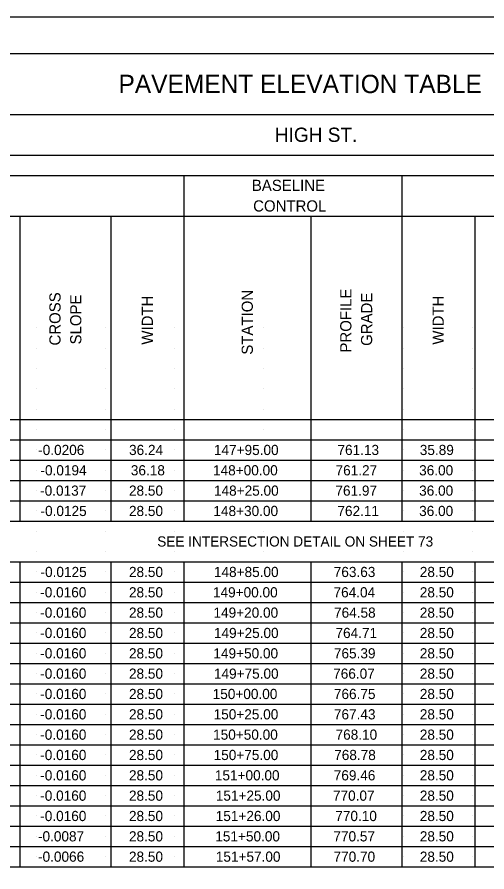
# Model space of a CAD drawing. Extents: x -15.4 to 18.6, y -12.6 to 9.4.
# Drawn here: x -2.5 to 3.96, y -2.38 to 9.39 of the extents above; entities that cross this region are included whole.
import ezdxf

# ---------------------------------------------------------------- set-up
doc = ezdxf.new("R2010")
doc.units = 0
for name, color, linetype in [('SH_Border', 7, 'Continuous'), ('SH_Cut_Line', 7, 'Continuous'), ('SH_Data', 7, 'Continuous'), ('SH_Text', 7, 'Continuous')]:
    doc.layers.add(name, color=color, linetype=linetype)

msp = doc.modelspace()

# ---------------------------------------------------------------- linework, layer by layer
at = {"layer": 'SH_Border'}
msp.add_lwpolyline([(-13.357, 8.888), (18.143, 8.888), (18.143, -12.112), (-13.357, -12.112)], close=True, dxfattribs=at)
at = {"layer": 'SH_Cut_Line'}
msp.add_lwpolyline([(-15.357, -12.612), (18.643, -12.612), (18.643, 9.388), (-15.357, 9.388)], close=True, dxfattribs=at)
at = {"layer": 'SH_Data'}
for p, q in [((-10.059, 8.888), (13.939, 8.888)), ((-8.906, 8.048), (12.061, 8.048)), ((-8.906, 7.488), (12.061, 7.488)), ((-10.059, 7.208), (13.939, 7.208)), ((-0.21, 7.208), (-0.21, 2.448)), ((2.788, 7.208), (2.788, 2.448)), ((-10.059, 6.648), (12.637, 6.648)), ((-2.466, 6.648), (-2.466, 2.448)), ((-1.214, 6.648), (-1.214, 2.448)), ((1.536, 6.648), (1.536, 2.448)), ((3.793, 6.648), (3.793, 2.448)), ((-2.232, 5.108), (-2.232, 5.108)), ((-1.282, 5.108), (-1.282, 5.108)), ((-0.332, 5.108), (-0.332, 5.108)), ((0.893, 5.108), (0.893, 5.108)), ((2.818, 5.108), (2.818, 5.108)), ((3.768, 5.108), (3.768, 5.108)), ((-2.232, 4.828), (-2.232, 4.828)), ((-1.282, 4.828), (-1.282, 4.828)), ((-0.332, 4.828), (-0.332, 4.828)), ((0.893, 4.828), (0.893, 4.828)), ((2.818, 4.828), (2.818, 4.828)), ((3.768, 4.828), (3.768, 4.828)), ((-2.232, 4.548), (-2.232, 4.548)), ((-1.282, 4.548), (-1.282, 4.548)), ((-0.332, 4.548), (-0.332, 4.548)), ((0.893, 4.548), (0.893, 4.548)), ((2.818, 4.548), (2.818, 4.548)), ((3.768, 4.548), (3.768, 4.548)), ((-2.232, 4.268), (-2.232, 4.268)), ((-1.282, 4.268), (-1.282, 4.268)), ((-0.332, 4.268), (-0.332, 4.268)), ((0.893, 4.268), (0.893, 4.268)), ((2.818, 4.268), (2.818, 4.268)), ((3.768, 4.268), (3.768, 4.268)), ((-2.232, 3.988), (-2.232, 3.988)), ((-1.282, 3.988), (-1.282, 3.988)), ((-0.332, 3.988), (-0.332, 3.988)), ((0.893, 3.988), (0.893, 3.988)), ((2.818, 3.988), (2.818, 3.988)), ((3.768, 3.988), (3.768, 3.988)), ((-10.059, 3.848), (13.939, 3.848)), ((-2.232, 3.708), (-2.232, 3.708)), ((-1.282, 3.708), (-1.282, 3.708)), ((-0.332, 3.708), (-0.332, 3.708)), ((0.893, 3.708), (0.893, 3.708)), ((2.818, 3.708), (2.818, 3.708)), ((3.768, 3.708), (3.768, 3.708)), ((-10.059, 3.568), (13.939, 3.568)), ((-2.232, 3.428), (-2.232, 3.428)), ((-1.282, 3.428), (-1.282, 3.428)), ((-0.332, 3.428), (-0.332, 3.428)), ((0.893, 3.428), (0.893, 3.428)), ((2.818, 3.428), (2.818, 3.428)), ((3.768, 3.428), (3.768, 3.428)), ((-10.059, 3.288), (13.939, 3.288)), ((-2.232, 3.148), (-2.232, 3.148)), ((-1.282, 3.148), (-1.282, 3.148)), ((-0.332, 3.148), (-0.332, 3.148)), ((0.893, 3.148), (0.893, 3.148)), ((2.818, 3.148), (2.818, 3.148)), ((3.768, 3.148), (3.768, 3.148)), ((-10.059, 3.008), (13.939, 3.008)), ((-2.232, 2.868), (-2.232, 2.868)), ((-1.282, 2.868), (-1.282, 2.868)), ((-0.332, 2.868), (-0.332, 2.868)), ((0.893, 2.868), (0.893, 2.868)), ((2.818, 2.868), (2.818, 2.868)), ((3.768, 2.868), (3.768, 2.868)), ((-10.059, 2.728), (13.939, 2.728)), ((-2.232, 2.588), (-2.232, 2.588)), ((-1.282, 2.588), (-1.282, 2.588)), ((-0.332, 2.588), (-0.332, 2.588)), ((0.893, 2.588), (0.893, 2.588)), ((2.818, 2.588), (2.818, 2.588)), ((3.768, 2.588), (3.768, 2.588)), ((-10.059, 2.448), (13.939, 2.448)), ((-2.232, 2.308), (-2.232, 2.308)), ((-1.282, 2.308), (-1.282, 2.308)), ((-0.332, 2.308), (-0.332, 2.308)), ((0.893, 2.308), (0.893, 2.308)), ((2.818, 2.308), (2.818, 2.308)), ((3.768, 2.308), (3.768, 2.308)), ((-2.232, 2.028), (-2.232, 2.028)), ((-1.282, 2.028), (-1.282, 2.028)), ((-0.332, 2.028), (-0.332, 2.028)), ((0.893, 2.028), (0.893, 2.028)), ((2.818, 2.028), (2.818, 2.028)), ((3.768, 2.028), (3.768, 2.028)), ((-10.059, 1.888), (13.939, 1.888)), ((-2.466, 1.888), (-2.466, -2.312)), ((-1.214, 1.888), (-1.214, -2.312)), ((-0.21, 1.888), (-0.21, -2.312)), ((1.536, 1.888), (1.536, -2.312)), ((2.788, 1.888), (2.788, -2.312)), ((3.793, 1.888), (3.793, -2.312)), ((-2.232, 1.748), (-2.232, 1.748)), ((-1.282, 1.748), (-1.282, 1.748)), ((-0.332, 1.748), (-0.332, 1.748)), ((0.893, 1.748), (0.893, 1.748)), ((2.818, 1.748), (2.818, 1.748)), ((3.768, 1.748), (3.768, 1.748)), ((-10.059, 1.608), (13.939, 1.608)), ((-2.232, 1.468), (-2.232, 1.468)), ((-1.282, 1.468), (-1.282, 1.468)), ((-0.332, 1.468), (-0.332, 1.468)), ((0.893, 1.468), (0.893, 1.468)), ((2.818, 1.468), (2.818, 1.468)), ((3.768, 1.468), (3.768, 1.468)), ((-10.059, 1.328), (13.939, 1.328)), ((-2.232, 1.188), (-2.232, 1.188)), ((-1.282, 1.188), (-1.282, 1.188)), ((-0.332, 1.188), (-0.332, 1.188)), ((0.893, 1.188), (0.893, 1.188)), ((2.818, 1.188), (2.818, 1.188)), ((3.768, 1.188), (3.768, 1.188)), ((-10.059, 1.048), (13.939, 1.048)), ((-2.232, 0.908), (-2.232, 0.908)), ((-1.282, 0.908), (-1.282, 0.908)), ((-0.332, 0.908), (-0.332, 0.908)), ((0.893, 0.908), (0.893, 0.908)), ((2.818, 0.908), (2.818, 0.908)), ((3.768, 0.908), (3.768, 0.908)), ((-10.059, 0.768), (13.939, 0.768)), ((-2.232, 0.628), (-2.232, 0.628)), ((-1.282, 0.628), (-1.282, 0.628)), ((-0.332, 0.628), (-0.332, 0.628)), ((0.893, 0.628), (0.893, 0.628)), ((2.818, 0.628), (2.818, 0.628)), ((3.768, 0.628), (3.768, 0.628)), ((-10.059, 0.488), (13.939, 0.488)), ((-2.232, 0.348), (-2.232, 0.348)), ((-1.282, 0.348), (-1.282, 0.348)), ((-0.332, 0.348), (-0.332, 0.348)), ((0.893, 0.348), (0.893, 0.348)), ((2.818, 0.348), (2.818, 0.348)), ((3.768, 0.348), (3.768, 0.348)), ((-10.059, 0.208), (13.939, 0.208)), ((-2.232, 0.068), (-2.232, 0.068)), ((-1.282, 0.068), (-1.282, 0.068)), ((-0.332, 0.068), (-0.332, 0.068)), ((0.893, 0.068), (0.893, 0.068)), ((2.818, 0.068), (2.818, 0.068)), ((3.768, 0.068), (3.768, 0.068)), ((-10.059, -0.072), (13.939, -0.072)), ((-2.232, -0.212), (-2.232, -0.212)), ((-1.282, -0.212), (-1.282, -0.212)), ((-0.332, -0.212), (-0.332, -0.212)), ((0.893, -0.212), (0.893, -0.212)), ((2.818, -0.212), (2.818, -0.212)), ((3.768, -0.212), (3.768, -0.212)), ((-10.059, -0.352), (13.939, -0.352)), ((-2.232, -0.492), (-2.232, -0.492)), ((-1.282, -0.492), (-1.282, -0.492)), ((-0.332, -0.492), (-0.332, -0.492)), ((0.893, -0.492), (0.893, -0.492)), ((2.818, -0.492), (2.818, -0.492)), ((3.768, -0.492), (3.768, -0.492)), ((-10.059, -0.632), (13.939, -0.632)), ((-2.232, -0.772), (-2.232, -0.772)), ((-1.282, -0.772), (-1.282, -0.772)), ((-0.332, -0.772), (-0.332, -0.772)), ((0.893, -0.772), (0.893, -0.772)), ((2.818, -0.772), (2.818, -0.772)), ((3.768, -0.772), (3.768, -0.772)), ((-10.059, -0.912), (13.939, -0.912)), ((-2.232, -1.052), (-2.232, -1.052)), ((-1.282, -1.052), (-1.282, -1.052)), ((-0.332, -1.052), (-0.332, -1.052)), ((0.893, -1.052), (0.893, -1.052)), ((2.818, -1.052), (2.818, -1.052)), ((3.768, -1.052), (3.768, -1.052)), ((-10.059, -1.192), (13.939, -1.192)), ((-2.232, -1.332), (-2.232, -1.332)), ((-1.282, -1.332), (-1.282, -1.332)), ((-0.332, -1.332), (-0.332, -1.332)), ((0.893, -1.332), (0.893, -1.332)), ((2.818, -1.332), (2.818, -1.332)), ((3.768, -1.332), (3.768, -1.332)), ((-10.059, -1.472), (13.939, -1.472)), ((-2.232, -1.612), (-2.232, -1.612)), ((-1.282, -1.612), (-1.282, -1.612)), ((-0.332, -1.612), (-0.332, -1.612)), ((0.893, -1.612), (0.893, -1.612)), ((2.818, -1.612), (2.818, -1.612)), ((3.768, -1.612), (3.768, -1.612)), ((-10.059, -1.752), (13.939, -1.752)), ((-2.232, -1.892), (-2.232, -1.892)), ((-1.282, -1.892), (-1.282, -1.892)), ((-0.332, -1.892), (-0.332, -1.892)), ((0.893, -1.892), (0.893, -1.892)), ((2.818, -1.892), (2.818, -1.892)), ((3.768, -1.892), (3.768, -1.892)), ((-10.059, -2.032), (13.939, -2.032)), ((-2.232, -2.172), (-2.232, -2.172)), ((-1.282, -2.172), (-1.282, -2.172)), ((-0.332, -2.172), (-0.332, -2.172)), ((0.893, -2.172), (0.893, -2.172)), ((2.818, -2.172), (2.818, -2.172)), ((3.768, -2.172), (3.768, -2.172)), ((-10.059, -2.312), (13.939, -2.312))]:
    msp.add_line(p, q, dxfattribs=at)

# ---------------------------------------------------------------- texts
at = {"layer": 'SH_Text'}
for s, height, p in [('PAVEMENT ELEVATION TABLE', 0.252, (-1.109, 8.342)), ('HIGH ST.', 0.196, (1.042, 7.67)), ('BASELINE', 0.154, (0.726, 6.994)), ('CONTROL', 0.154, (0.744, 6.711)), ('-0.0206', 0.14, (-2.214, 3.358)), ('36.24', 0.14, (-0.964, 3.358)), ('147+95.00', 0.14, (0.204, 3.358)), ('761.13', 0.14, (1.904, 3.358)), ('35.89', 0.14, (3.037, 3.358)), ('-0.0194', 0.14, (-2.183, 3.078)), ('36.18', 0.14, (-0.939, 3.078)), ('148+00.00', 0.14, (0.192, 3.078)), ('761.27', 0.14, (1.878, 3.078)), ('36.00', 0.14, (3.028, 3.078)), ('-0.0137', 0.14, (-2.187, 2.798)), ('28.50', 0.14, (-0.965, 2.798)), ('148+25.00', 0.14, (0.205, 2.798)), ('761.97', 0.14, (1.876, 2.798)), ('36.00', 0.14, (3.028, 2.798)), ('-0.0125', 0.14, (-2.182, 2.518)), ('28.50', 0.14, (-0.965, 2.518)), ('148+30.00', 0.14, (0.197, 2.518)), ('762.11', 0.14, (1.903, 2.518)), ('36.00', 0.14, (3.028, 2.518)), ('SEE INTERSECTION DETAIL ON SHEET 73', 0.14, (-0.576, 2.098)), ('-0.0125', 0.14, (-2.182, 1.678)), ('28.50', 0.14, (-0.965, 1.678)), ('148+85.00', 0.14, (0.204, 1.678)), ('763.63', 0.14, (1.853, 1.678)), ('28.50', 0.14, (3.037, 1.678)), ('-0.0160', 0.14, (-2.186, 1.398)), ('28.50', 0.14, (-0.965, 1.398)), ('149+00.00', 0.14, (0.191, 1.398)), ('764.04', 0.14, (1.85, 1.398)), ('28.50', 0.14, (3.037, 1.398)), ('-0.0160', 0.14, (-2.186, 1.118)), ('28.50', 0.14, (-0.965, 1.118)), ('149+20.00', 0.14, (0.198, 1.118)), ('764.58', 0.14, (1.857, 1.118)), ('28.50', 0.14, (3.037, 1.118)), ('-0.0160', 0.14, (-2.186, 0.838)), ('28.50', 0.14, (-0.965, 0.838)), ('149+25.00', 0.14, (0.204, 0.838)), ('764.71', 0.14, (1.877, 0.838)), ('28.50', 0.14, (3.037, 0.838)), ('-0.0160', 0.14, (-2.186, 0.558)), ('28.50', 0.14, (-0.965, 0.558)), ('149+50.00', 0.14, (0.197, 0.558)), ('765.39', 0.14, (1.855, 0.558)), ('28.50', 0.14, (3.037, 0.558)), ('-0.0160', 0.14, (-2.186, 0.278)), ('28.50', 0.14, (-0.965, 0.278)), ('149+75.00', 0.14, (0.204, 0.278)), ('766.07', 0.14, (1.845, 0.278)), ('28.50', 0.14, (3.037, 0.278)), ('-0.0160', 0.14, (-2.186, -0.002)), ('28.50', 0.14, (-0.965, -0.002)), ('150+00.00', 0.14, (0.187, -0.002)), ('766.75', 0.14, (1.855, -0.002)), ('28.50', 0.14, (3.037, -0.002)), ('-0.0160', 0.14, (-2.186, -0.282)), ('28.50', 0.14, (-0.965, -0.282)), ('150+25.00', 0.14, (0.2, -0.282)), ('767.43', 0.14, (1.855, -0.282)), ('28.50', 0.14, (3.037, -0.282)), ('-0.0160', 0.14, (-2.186, -0.562)), ('28.50', 0.14, (-0.965, -0.562)), ('150+50.00', 0.14, (0.193, -0.562)), ('768.10', 0.14, (1.878, -0.562)), ('28.50', 0.14, (3.037, -0.562)), ('-0.0160', 0.14, (-2.186, -0.842)), ('28.50', 0.14, (-0.965, -0.842)), ('150+75.00', 0.14, (0.2, -0.842)), ('768.78', 0.14, (1.859, -0.842)), ('28.50', 0.14, (3.037, -0.842)), ('-0.0160', 0.14, (-2.186, -1.122)), ('28.50', 0.14, (-0.965, -1.122)), ('151+00.00', 0.14, (0.217, -1.122)), ('769.46', 0.14, (1.853, -1.122)), ('28.50', 0.14, (3.037, -1.122)), ('-0.0160', 0.14, (-2.186, -1.402)), ('28.50', 0.14, (-0.965, -1.402)), ('151+25.00', 0.14, (0.23, -1.402)), ('770.07', 0.14, (1.842, -1.402)), ('28.50', 0.14, (3.037, -1.402)), ('-0.0160', 0.14, (-2.186, -1.682)), ('28.50', 0.14, (-0.965, -1.682)), ('151+26.00', 0.14, (0.229, -1.682)), ('770.10', 0.14, (1.874, -1.682)), ('28.50', 0.14, (3.037, -1.682)), ('-0.0087', 0.14, (-2.217, -1.962)), ('28.50', 0.14, (-0.965, -1.962)), ('151+50.00', 0.14, (0.223, -1.962)), ('770.57', 0.14, (1.848, -1.962)), ('28.50', 0.14, (3.037, -1.962)), ('-0.0066', 0.14, (-2.216, -2.242)), ('28.50', 0.14, (-0.965, -2.242)), ('151+57.00', 0.14, (0.23, -2.242)), ('770.70', 0.14, (1.85, -2.242)), ('28.50', 0.14, (3.037, -2.242))]:
    msp.add_text(s, height=height, dxfattribs=at).set_placement(p)
for s, p in [('CROSS', (-1.906, 4.866)), ('SLOPE', (-1.62, 4.881)), ('WIDTH', (-0.635, 4.878)), ('STATION', (0.74, 4.74)), ('PROFILE', (2.096, 4.769)), ('GRADE', (2.382, 4.861)), ('WIDTH', (3.367, 4.878))]:
    msp.add_text(s, height=0.154, rotation=90, dxfattribs=at).set_placement(p)

doc.saveas('drawing.dxf')
